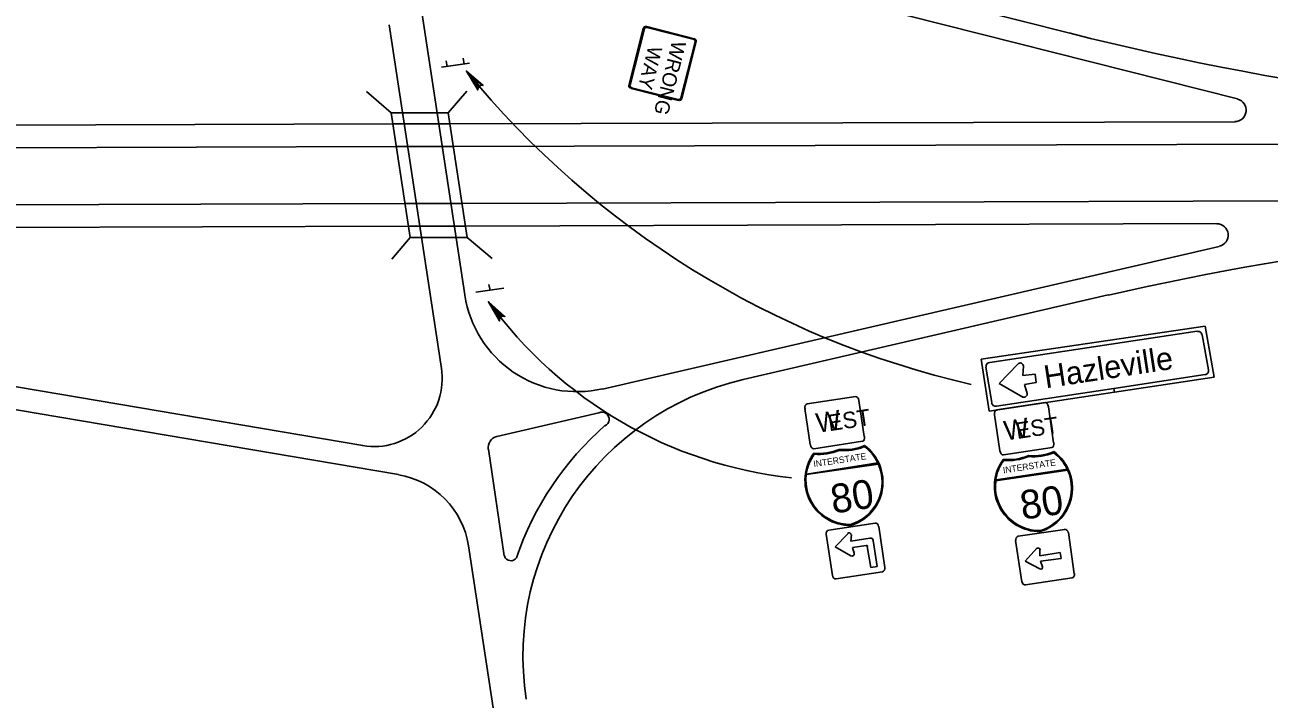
# Model space of a CAD drawing. Extents: x 640994 to 644422, y 298458 to 299646.
# Drawn here: x 642997.9 to 643292.3, y 299271.4 to 299430.9 of the extents above; entities that cross this region are included whole.
import ezdxf

# ---------------------------------------------------------------- set-up
doc = ezdxf.new("R2010")
doc.units = 0
doc.layers.add('2', color=7, linetype='Continuous')

msp = doc.modelspace()

# ---------------------------------------------------------------- linework, layer by layer
at = {"layer": '2'}
for p, q in [((643244.81, 299429), (643099.31, 299465.88)), ((643284.81, 299413.38), (643110.81, 299457.38)), ((643090.94, 299439.38), (643101.94, 299367)), ((643084.06, 299430.88), (643096.44, 299349.63)), ((643144.94, 299430.5), (643156.19, 299427.63)), ((643145.06, 299430.25), (643155.94, 299427.5)), ((643140.81, 299416.5), (643144.19, 299430.13)), ((643141.06, 299416.63), (643144.44, 299430)), ((643156.44, 299426.88), (643153.06, 299413.63)), ((643156.69, 299427), (643153.31, 299413.38)), ((643103.06, 299421.88), (643096.44, 299420.88)), ((643097.81, 299421), (643097.56, 299422.38)), ((643101.81, 299421.63), (643101.56, 299423)), ((643148.69, 299421.75), (643148.69, 299421.75)), ((643152.56, 299413), (643141.31, 299415.88)), ((643152.44, 299413.25), (643141.44, 299416)), ((643078.69, 299415.13), (643084.56, 299410.13)), ((643102.44, 299415.25), (643098.06, 299410.13)), ((643089.06, 299380.63), (643084.56, 299410.13)), ((643084.56, 299410.13), (643098.06, 299410.13)), ((643098.06, 299410.13), (643102.56, 299380.63)), ((642815.56, 299406.63), (643084.94, 299407.5)), ((643084.94, 299407.5), (643098.56, 299407.5)), ((643087.69, 299407.5), (643087.69, 299407.5)), ((643095.81, 299407.5), (643095.81, 299407.5)), ((643098.56, 299407.5), (643284.19, 299408)), ((642716.31, 299401.01), (643085.69, 299402.13)), ((643085.69, 299402.13), (643099.31, 299402.13)), ((643099.31, 299402.13), (643502.31, 299403.27)), ((643101.31, 299388.63), (643502.31, 299389.89)), ((642716.31, 299387.51), (643087.81, 299388.63)), ((643087.81, 299388.63), (643101.31, 299388.63)), ((642808.19, 299382.5), (643088.56, 299383.25)), ((643088.56, 299383.25), (643102.19, 299383.25)), ((643091.31, 299383.25), (643091.31, 299383.25)), ((643099.44, 299383.25), (643099.44, 299383.25)), ((643102.19, 299383.25), (643279.94, 299383.88)), ((643084.69, 299375.5), (643089.06, 299380.63)), ((643102.56, 299380.63), (643089.06, 299380.63)), ((643108.44, 299375.63), (643102.56, 299380.63)), ((643134.56, 299344.75), (643280.44, 299378.5)), ((642807.81, 299377.13), (643077.81, 299331.38)), ((642801.94, 299372.63), (643086.31, 299324.5)), ((643111.19, 299368.63), (643104.56, 299367.63)), ((643107.94, 299368.13), (643107.69, 299369.5)), ((643167.81, 299347), (643254.19, 299367)), ((643277.15, 299359.66), (643224.15, 299351.79)), ((643279.27, 299347.54), (643277.15, 299359.66)), ((643226.15, 299351.04), (643275.27, 299358.41)), ((643276.4, 299357.54), (643277.9, 299349.29)), ((643224.15, 299351.79), (643226.02, 299339.54)), ((643226.65, 299341.54), (643225.27, 299349.91)), ((643228.4, 299346.04), (643232.77, 299350.66)), ((643234.15, 299350.16), (643234.02, 299347.91)), ((643234.02, 299347.91), (643236.9, 299348.29)), ((643236.9, 299348.29), (643237.15, 299346.29)), ((643277.15, 299348.16), (643255.52, 299344.88)), ((643255.52, 299344.88), (643227.77, 299340.66)), ((643234.02, 299342.79), (643228.4, 299346.04)), ((643237.15, 299346.29), (643234.4, 299345.79)), ((643234.4, 299345.79), (643235.02, 299343.66)), ((643255.67, 299343.99), (643255.52, 299344.88)), ((643255.52, 299344.88), (643255.67, 299343.99)), ((643255.67, 299343.99), (643279.27, 299347.54)), ((643182.94, 299341.25), (643194.44, 299343)), ((643195.19, 299342), (643196.44, 299333.5)), ((643226.02, 299339.54), (643255.67, 299343.99)), ((643109.56, 299333.5), (643133.69, 299339.13)), ((643183.69, 299331.63), (643182.44, 299340.13)), ((643227.77, 299339.79), (643239.27, 299341.54)), ((643240.02, 299340.54), (643241.27, 299332.04)), ((643189.44, 299336.75), (643189.44, 299336.75)), ((643228.52, 299330.16), (643227.27, 299338.66)), ((643234.27, 299335.29), (643234.27, 299335.29)), ((643107.56, 299330.5), (643111.31, 299305.25)), ((643196.06, 299332.38), (643184.56, 299330.63)), ((643190.56, 299330.25), (643190.56, 299330.25)), ((643196.44, 299331.13), (643196.44, 299331.13)), ((643240.9, 299330.91), (643229.4, 299329.16)), ((643199.69, 299327.25), (643182.81, 299324.63)), ((643184.69, 299329.38), (643184.69, 299329.38)), ((643229.52, 299327.91), (643229.52, 299327.91)), ((643235.4, 299328.79), (643235.4, 299328.79)), ((643241.27, 299329.66), (643241.27, 299329.66)), ((643182.69, 299324.5), (643199.81, 299327)), ((643227.52, 299323.04), (643244.65, 299325.54)), ((643244.52, 299325.79), (643227.65, 299323.29)), ((643191.94, 299321.5), (643191.94, 299321.5)), ((643236.77, 299320.04), (643236.77, 299320.04)), ((643188.06, 299311.38), (643199.06, 299313)), ((643188.06, 299311.38), (643199.06, 299313)), ((643188.94, 299300.63), (643187.44, 299310.38)), ((643188.94, 299300.63), (643187.44, 299310.38)), ((643192.56, 299310.5), (643189.56, 299307.38)), ((643193.31, 299308.75), (643193.44, 299310.25)), ((643197.81, 299309.5), (643193.31, 299308.75)), ((643199.94, 299312.25), (643201.31, 299302.5)), ((643199.94, 299312.25), (643201.31, 299302.5)), ((643232.9, 299309.91), (643243.9, 299311.54)), ((643232.9, 299309.91), (643243.9, 299311.54)), ((643232.9, 299309.91), (643243.9, 299311.54)), ((643244.77, 299310.79), (643246.15, 299301.04)), ((643244.77, 299310.79), (643246.15, 299301.04)), ((643244.77, 299310.79), (643246.15, 299301.04)), ((643102.81, 299307.63), (643139.56, 299066.63)), ((643189.56, 299307.38), (643193.31, 299305.25)), ((643193.69, 299307.25), (643196.94, 299307.75)), ((643194.06, 299305.88), (643193.69, 299307.25)), ((643197.19, 299307.5), (643198.06, 299302.5)), ((643198.56, 299308.88), (643198.56, 299308.88)), ((643199.56, 299302.75), (643198.56, 299308.88)), ((643233.77, 299299.16), (643232.27, 299308.91)), ((643233.77, 299299.16), (643232.27, 299308.91)), ((643233.77, 299299.16), (643232.27, 299308.91)), ((643237.29, 299307.06), (643234.54, 299304.06)), ((643238.04, 299305.31), (643238.04, 299306.69)), ((643194.44, 299306.38), (643194.44, 299306.38)), ((643194.44, 299306.38), (643194.44, 299306.38)), ((643234.54, 299304.06), (643238.04, 299302.19)), ((643242.79, 299306.06), (643238.04, 299305.31)), ((643238.16, 299304.06), (643243.04, 299304.69)), ((643238.66, 299302.69), (643238.16, 299304.06)), ((643239.27, 299305.04), (643239.27, 299305.04)), ((643243.04, 299304.69), (643242.79, 299306.06)), ((643200.81, 299301.5), (643189.81, 299299.88)), ((643200.81, 299301.5), (643189.81, 299299.88)), ((643198.06, 299302.5), (643199.56, 299302.75)), ((643245.65, 299300.04), (643234.65, 299298.41)), ((643245.65, 299300.04), (643234.65, 299298.41)), ((643245.65, 299300.04), (643234.65, 299298.41))]:
    msp.add_line(p, q, dxfattribs=at)
for points in [[(643105.08, 299415.86), (643105.25, 299416.28), (643102.36, 299419.96), (643105.08, 299415.86), (643105.02, 299415.5), (643102.36, 299419.96), (643105.56, 299416.5), (643105.94, 299416.61), (643102.36, 299419.96), (643106.29, 299416.55), (643105.94, 299416.61)], [(643110.19, 299361.25), (643110.31, 299361.63), (643107.56, 299365.38), (643110.19, 299361.25), (643110.19, 299360.88), (643107.56, 299365.38), (643110.69, 299361.88), (643111.06, 299362), (643107.56, 299365.38), (643111.44, 299361.88), (643111.06, 299362)]]:
    msp.add_lwpolyline(points, dxfattribs=at)
for centre, radius, start, end in [((643409.91, 300080.28), 671.88, 255.77937, 270.1682), ((643270.22, 299557.12), 216.77, 219.2532, 257.0731), ((643284.14, 299410.72), 2.69, 270.1683, 75.7793), ((643405.54, 298712.33), 671.88, 90.1683, 103.0152), ((643279.88, 299381.15), 2.69, 283.0152, 90.1683), ((643128.53, 299370.99), 26.87, 188.6538, 283.0152), ((643190.44, 299425.4), 102.28, 215.9181, 263.7348), ((643275.42, 299357.38), 1, 6.2199, 97.995), ((643226.29, 299350.07), 1, 97.9608, 187.1226), ((643233.38, 299350.17), 0.745, 356.9014, 140.8081), ((643080.49, 299347.26), 16.13, 260.3831, 8.6537), ((643276.94, 299349.1), 1, 279.2127, 9.6981), ((643182.92, 299281.5), 67.19, 103.0152, 188.6538), ((643234.27, 299343.53), 0.745, 239.2297, 16.7538), ((643134.47, 299337.6), 1.67, 290.9294, 117.2399), ((643227.58, 299341.69), 1, 189.9657, 278.3786), ((643182.92, 299281.5), 72.56, 131.1224, 161.2817), ((643110.17, 299330.88), 2.69, 103.0154, 188.6538), ((643185.73, 299341.83), 12.33, 264.4038, 292.9038), ((643185.73, 299341.83), 12.56, 264.9943, 292.6428), ((643191.73, 299342.74), 12.33, 264.4038, 292.9038), ((643191.73, 299342.74), 12.56, 264.6648, 292.3133), ((643190.17, 299322.74), 10.73, 286.7839, 53.6538), ((643190.17, 299322.74), 10.51, 25.4466, 52.9614), ((643193.17, 299323.2), 10.73, 143.6538, 270.5237), ((643193.17, 299323.2), 10.51, 144.3462, 171.8611), ((643238, 299321.75), 10.73, 143.6538, 270.5237), ((643238, 299321.75), 10.51, 144.3462, 171.8611), ((643230.56, 299340.38), 12.33, 264.4038, 292.9038), ((643230.56, 299340.38), 12.56, 264.9943, 292.6428), ((643236.56, 299341.29), 12.33, 264.4038, 292.9038), ((643236.56, 299341.29), 12.56, 264.6648, 292.3133), ((643235, 299321.29), 10.73, 286.7839, 53.6538), ((643235, 299321.29), 10.51, 25.4466, 52.9614), ((643082.9, 299304.6), 20.16, 8.6538, 80.3831), ((643193.17, 299323.2), 10.51, 173.1407, 270.5237), ((643190.17, 299322.74), 10.51, 286.7839, 24.1669), ((643235, 299321.29), 10.51, 286.7839, 24.1669), ((643238, 299321.75), 10.51, 173.1407, 270.5237), ((643192.9, 299310.22), 0.502, 358.1291, 138.7947), ((643197.91, 299308.81), 0.672, 8.6538, 98.6538), ((643196.97, 299307.49), 0.269, 8.6538, 98.6538), ((643237.61, 299306.69), 0.46, 356.9014, 140.8081), ((643112.89, 299305.75), 1.63, 197.7979, 323.4245), ((643193.61, 299305.72), 0.502, 236.4996, 20.4062), ((643238.21, 299302.57), 0.46, 238.5129, 19.1785)]:
    msp.add_arc(centre, radius, start, end, dxfattribs=at)
for centre, major_axis, ratio, start_param, end_param in [((643144.84, 299430.01), (-0.625, 0.158), 0.777833, 4.712389, 6.283185), ((643144.99, 299429.82), (-0.578, 0.147), 0.777833, 4.712389, 6.283185), ((643155.87, 299427.06), (-0.578, 0.147), 0.777833, 3.141593, 4.712389), ((643156.09, 299427.16), (-0.625, 0.158), 0.777833, 3.141593, 4.712389), ((643141.39, 299416.39), (0.625, -0.158), 0.777833, 3.141593, 4.712389), ((643141.61, 299416.49), (0.578, -0.147), 0.777833, 3.141593, 4.712389), ((643152.49, 299413.73), (0.578, -0.147), 0.777833, 4.712389, 6.283185), ((643152.64, 299413.54), (0.625, -0.158), 0.777833, 4.712389, 6.283185), ((643194.57, 299341.92), (-0.16, 1.06), 0.6, 4.712389, 6.283185), ((643183.09, 299340.17), (0.16, -1.06), 0.6, 3.141593, 4.712389), ((643227.92, 299338.72), (0.16, -1.06), 0.6, 3.141593, 4.712389), ((643239.4, 299340.47), (-0.16, 1.06), 0.6, 4.712389, 6.283185), ((643195.86, 299333.42), (-0.16, 1.06), 0.6, 3.141593, 4.712389), ((643184.38, 299331.67), (0.16, -1.06), 0.6, 4.712389, 6.283185), ((643229.21, 299330.22), (0.16, -1.06), 0.6, 4.712389, 6.283185), ((643240.69, 299331.97), (-0.16, 1.06), 0.6, 3.141593, 4.712389), ((643199.17, 299312.11), (-0.14, 0.921), 0.769266, 4.712389, 6.283185), ((643199.17, 299312.11), (-0.14, 0.921), 0.769266, 4.712389, 6.283185), ((643188.19, 299310.44), (0.14, -0.921), 0.769266, 3.141593, 4.712389), ((643188.19, 299310.44), (0.14, -0.921), 0.769266, 3.141593, 4.712389), ((643233.02, 299308.99), (0.14, -0.921), 0.769266, 3.141593, 4.712389), ((643233.02, 299308.99), (0.14, -0.921), 0.769266, 3.141593, 4.712389), ((643233.02, 299308.99), (0.14, -0.921), 0.769266, 3.141593, 4.712389), ((643244, 299310.66), (-0.14, 0.921), 0.769266, 4.712389, 6.283185), ((643244, 299310.66), (-0.14, 0.921), 0.769266, 4.712389, 6.283185), ((643244, 299310.66), (-0.14, 0.921), 0.769266, 4.712389, 6.283185), ((643189.66, 299300.76), (0.14, -0.921), 0.769266, 4.712389, 6.283185), ((643189.66, 299300.76), (0.14, -0.921), 0.769266, 4.712389, 6.283185), ((643200.65, 299302.43), (-0.14, 0.921), 0.769266, 3.141593, 4.712389), ((643200.65, 299302.43), (-0.14, 0.921), 0.769266, 3.141593, 4.712389), ((643245.48, 299300.98), (-0.14, 0.921), 0.769266, 3.141593, 4.712389), ((643245.48, 299300.98), (-0.14, 0.921), 0.769266, 3.141593, 4.712389), ((643245.48, 299300.98), (-0.14, 0.921), 0.769266, 3.141593, 4.712389), ((643234.49, 299299.31), (0.14, -0.921), 0.769266, 4.712389, 6.283185), ((643234.49, 299299.31), (0.14, -0.921), 0.769266, 4.712389, 6.283185), ((643234.49, 299299.31), (0.14, -0.921), 0.769266, 4.712389, 6.283185)]:
    msp.add_ellipse(centre, major_axis=major_axis, ratio=ratio, start_param=start_param, end_param=end_param, dxfattribs=at)

# ---------------------------------------------------------------- texts
for s, height, rotation, p in [('WAY', 3.386, 255.7793, (643145.44, 299426.13)), ('WRONG', 3.385, 255.7793, (643151.06, 299427.38)), ('Hazleville ', 5.3752, 8.6538, (643239.4, 299344.91)), ('W', 4.63, 8.6525, (643185.44, 299334.38)), ('EST', 3.875, 8.6538, (643188.19, 299334.75)), ('W', 4.63, 8.6525, (643229.9, 299332.54)), ('EST', 3.875, 8.6538, (643232.65, 299332.91)), ('INTERSTATE', 1.517, 8.6538, (643184.56, 299326.25)), ('INTERSTATE', 1.517, 8.6538, (643229.4, 299324.79)), ('80', 6.829, 8.6538, (643189.06, 299315.25)), ('80', 6.829, 8.6538, (643233.9, 299313.79))]:
    msp.add_text(s, height=height, rotation=rotation, dxfattribs=at).set_placement(p)

doc.saveas('drawing.dxf')
